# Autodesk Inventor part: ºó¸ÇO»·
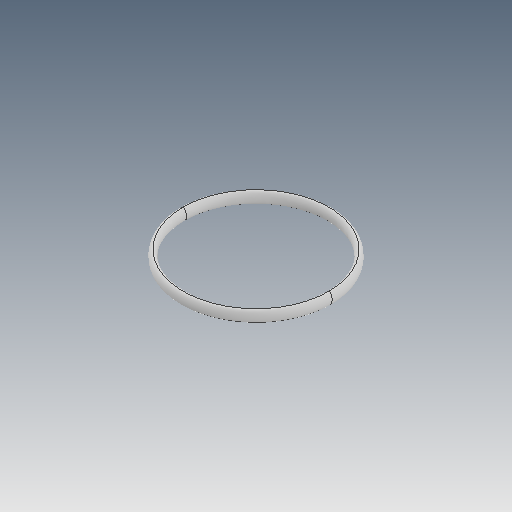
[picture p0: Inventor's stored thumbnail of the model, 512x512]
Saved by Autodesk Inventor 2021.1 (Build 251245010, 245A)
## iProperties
Created: 2019-04
Part Number: ºó¸ÇO»·
Material: Ogólny
Document SubType Name: Modeling
Designer: user
Density: 1 g/cm^3
Appearance: Domyślna
Author: user
Revision Number: ÈÎºÎ
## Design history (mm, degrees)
feature "ÊäÈë1"
node "Bryła1"
